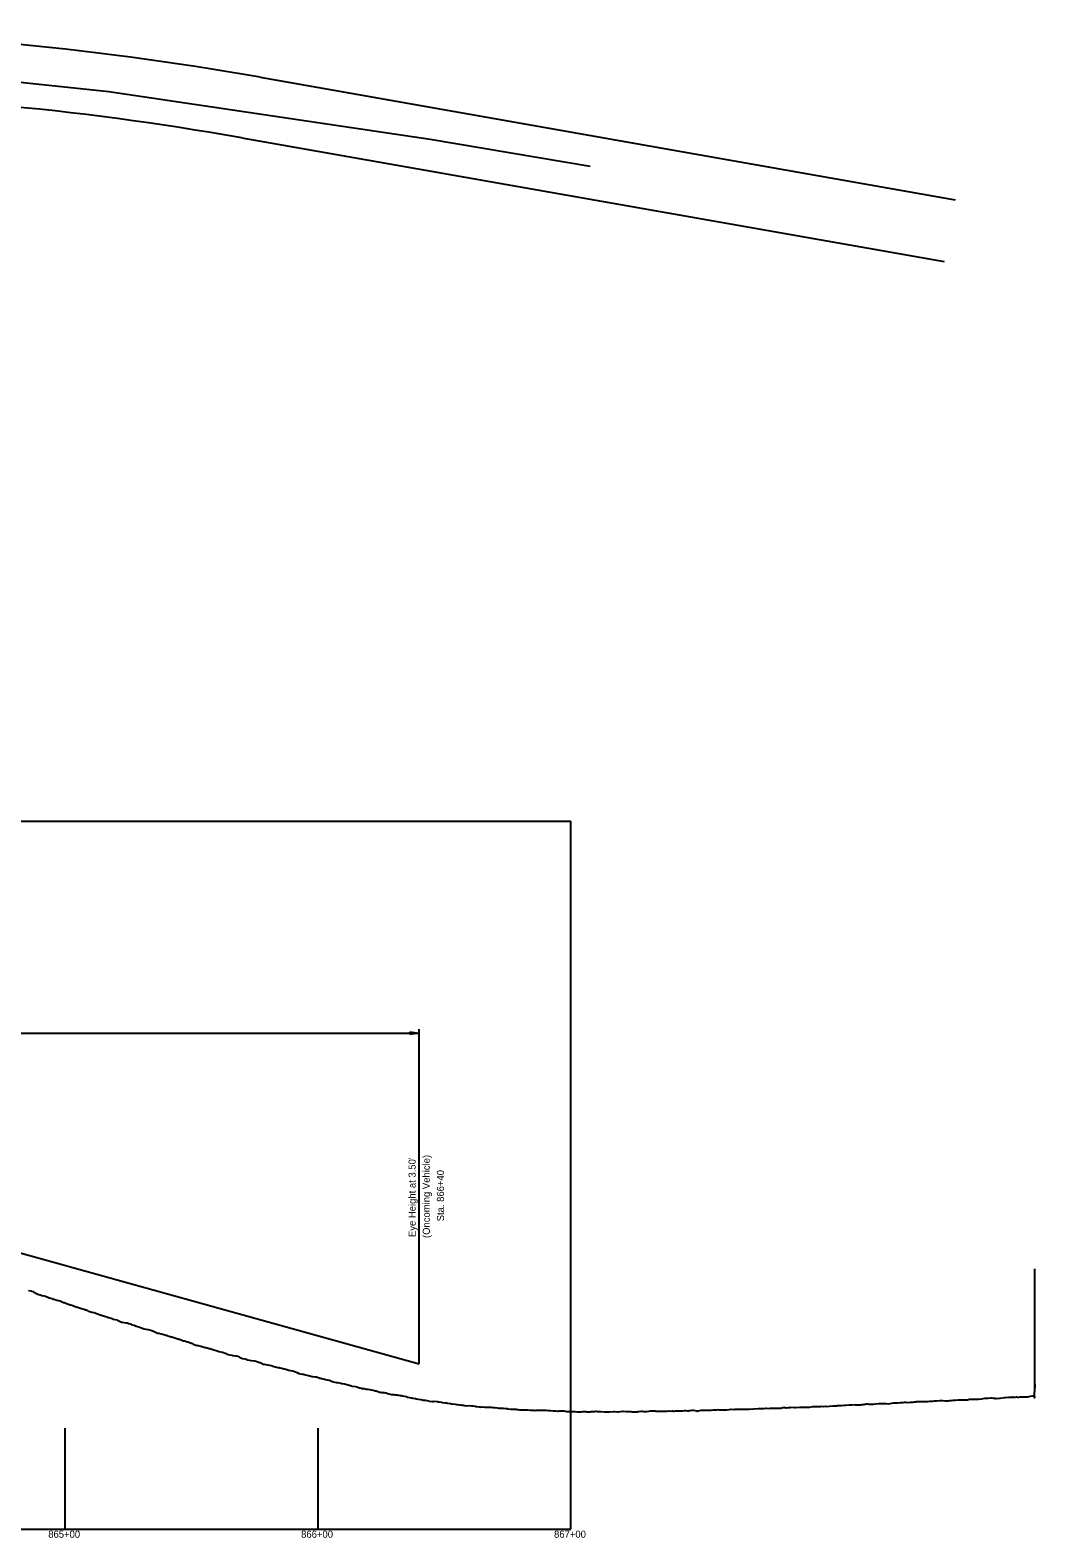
# Model space of a CAD drawing. Extents: x 115987 to 120394, y 324408 to 325987.
# Drawn here: x 119996 to 120394, y 325283 to 325879 of the extents above; entities that cross this region are included whole.
import ezdxf

# ---------------------------------------------------------------- set-up
doc = ezdxf.new("R2010")
doc.units = 0
for name, color, linetype in [('_CIVIL_CONSTRUCTION', 7, 'Continuous'), ('DR_Ditch', 7, 'Continuous'), ('DT_X_Spot_Elev', 7, 'Continuous'), ('SV_X_Text', 7, 'Continuous')]:
    doc.layers.add(name, color=color, linetype=linetype)

msp = doc.modelspace()

# ---------------------------------------------------------------- linework, layer by layer
at = {"layer": '_CIVIL_CONSTRUCTION'}
msp.add_lwpolyline([(119433.5, 325808.06), (119458.19, 325811.98), (119653.75, 325843.88), (119803.55, 325862.77), (119869.37, 325865.76), (119948.48, 325863.4), (120027.4, 325855.07), (120154.49, 325836.23), (120217.67, 325825.54)], dxfattribs=at)
at = {"layer": 'DR_Ditch'}
for p, q in [((119610.09, 325566.43), (120210.09, 325566.43)), ((120210.09, 325286.43), (120210.09, 325566.43)), ((119675.09, 325484.19), (120150.09, 325351.76)), ((119790.09, 325482.58), (120150.09, 325482.58)), ((120150.09, 325482.58), (120146.38, 325482.09)), ((120146.38, 325482.09), (120146.39, 325482.09)), ((120146.4, 325483.08), (120146.4, 325483.08)), ((120146.4, 325483.08), (120150.09, 325482.58)), ((120150.09, 325351.76), (120150.09, 325484.13)), ((120010.09, 325286.43), (120010.09, 325326.43)), ((120110.09, 325286.43), (120110.09, 325326.43)), ((119610.09, 325286.43), (120210.09, 325286.43))]:
    msp.add_line(p, q, dxfattribs=at)
msp.add_ellipse((120145.45, 325482.59), major_axis=(1.13, 0), ratio=0.8, start_param=5.69288, end_param=6.856679, dxfattribs=at)
at = {"layer": 'DT_X_Spot_Elev'}
msp.add_lwpolyline([(119995.57, 325380.85), (119996.69, 325380.64), (119996.75, 325380.63), (119996.78, 325380.62), (119997.48, 325380.41), (119997.61, 325380.34), (119998.8, 325379.67), (119999.33, 325379.35), (119999.33, 325379.35), (119999.33, 325379.35), (120000.62, 325378.94), (120000.71, 325378.9), (120000.92, 325378.89), (120001.61, 325378.76), (120002.21, 325378.64), (120002.31, 325378.61), (120002.34, 325378.6), (120002.62, 325378.47), (120002.96, 325378.31), (120003.74, 325377.96), (120003.93, 325377.87), (120004.82, 325377.61), (120005.28, 325377.46), (120005.71, 325377.34), (120006.37, 325377.15), (120006.77, 325377.04), (120007.44, 325376.89), (120007.54, 325376.87), (120008.09, 325376.68), (120008.43, 325376.55), (120008.86, 325376.35), (120009.44, 325376.1), (120009.71, 325376.02), (120010.08, 325375.91), (120010.63, 325375.66), (120011.35, 325375.38), (120011.45, 325375.36), (120011.83, 325375.21), (120012.37, 325375.11), (120013.12, 325374.83), (120013.66, 325374.69), (120013.8, 325374.65), (120014.04, 325374.55), (120014.89, 325374.26), (120015.01, 325374.22), (120015.76, 325373.98), (120016.58, 325373.73), (120016.61, 325373.72), (120016.62, 325373.71), (120017.66, 325373.43), (120018.16, 325373.2), (120018.26, 325373.16), (120018.36, 325373.12), (120019.23, 325372.68), (120019.85, 325372.49), (120019.96, 325372.45), (120020.21, 325372.39), (120020.71, 325372.27), (120021.49, 325372.12), (120021.52, 325372.11), (120021.52, 325372.11), (120022.21, 325371.88), (120022.93, 325371.58), (120023.29, 325371.46), (120023.9, 325371.21), (120023.91, 325371.21), (120024.02, 325371.18), (120024.35, 325371.08), (120024.82, 325370.93), (120025.15, 325370.83), (120025.18, 325370.82), (120025.62, 325370.67), (120026.53, 325370.38), (120027.07, 325370.21), (120027.32, 325370.15), (120028.24, 325369.83), (120028.5, 325369.73), (120028.99, 325369.55), (120029.06, 325369.53), (120030.6, 325369.2), (120030.66, 325369.19), (120030.68, 325369.18), (120030.78, 325369.13), (120032.37, 325368.34), (120032.68, 325368.25), (120034.05, 325368.04), (120034.35, 325368.02), (120034.41, 325368), (120034.56, 325367.97), (120035.69, 325367.59), (120036.3, 325367.45), (120036.39, 325367.41), (120037.2, 325367.17), (120037.4, 325367.11), (120038.21, 325366.77), (120038.23, 325366.77), (120038.3, 325366.74), (120039.17, 325366.45), (120039.23, 325366.43), (120039.85, 325366.19), (120040.91, 325365.73), (120041.02, 325365.69), (120041.03, 325365.69), (120041.13, 325365.66), (120041.33, 325365.6), (120042.82, 325365.43), (120042.87, 325365.42), (120042.89, 325365.41), (120043.95, 325365.11), (120044.43, 325364.96), (120044.57, 325364.92), (120044.59, 325364.92), (120044.7, 325364.88), (120045.07, 325364.7), (120046.06, 325364.21), (120046.26, 325364.12), (120046.29, 325364.12), (120046.58, 325364.01), (120046.62, 325364), (120046.63, 325363.99), (120047.1, 325363.91), (120048.09, 325363.74), (120048.25, 325363.68), (120049.18, 325363.38), (120049.89, 325363.18), (120050.11, 325363.11), (120050.54, 325362.96), (120051.64, 325362.58), (120051.9, 325362.55), (120052.31, 325362.45), (120053.48, 325362.05), (120053.81, 325361.92), (120055, 325361.61), (120055.15, 325361.56), (120055.31, 325361.53), (120055.58, 325361.45), (120055.95, 325361.3), (120056.77, 325360.98), (120057.05, 325360.93), (120057.26, 325360.89), (120058.03, 325360.63), (120058.48, 325360.5), (120058.57, 325360.49), (120059.01, 325360.36), (120059.96, 325360.04), (120060.16, 325359.97), (120060.37, 325359.85), (120060.74, 325359.65), (120061.78, 325359.24), (120061.94, 325359.2), (120062.05, 325359.19), (120062.44, 325359.13), (120062.81, 325359.04), (120063.73, 325358.84), (120063.91, 325358.77), (120064.11, 325358.69), (120064.55, 325358.55), (120065.46, 325358.31), (120065.73, 325358.23), (120066.21, 325358.1), (120067.07, 325357.87), (120067.26, 325357.83), (120068.46, 325357.49), (120068.6, 325357.44), (120068.74, 325357.4), (120068.91, 325357.34), (120069.85, 325357.03), (120070.19, 325356.91), (120070.58, 325356.78), (120070.8, 325356.75), (120072.36, 325356.46), (120073.78, 325355.85), (120074.07, 325355.72), (120074.29, 325355.61), (120074.46, 325355.55), (120075.97, 325355.24), (120076.1, 325355.21), (120076.4, 325355.17), (120077.39, 325355.02), (120077.66, 325354.95), (120077.78, 325354.95), (120078.35, 325354.79), (120079.23, 325354.32), (120079.35, 325354.28), (120079.6, 325354.19), (120080.23, 325353.99), (120080.35, 325353.97), (120081.2, 325353.81), (120081.72, 325353.6), (120081.98, 325353.49), (120082.12, 325353.45), (120083.03, 325353.22), (120083.48, 325353.19), (120083.54, 325353.18), (120084.81, 325353.07), (120084.86, 325353.05), (120085.05, 325353.05), (120086.24, 325352.64), (120086.64, 325352.49), (120086.71, 325352.46), (120087.41, 325352.16), (120088.45, 325351.74), (120088.82, 325351.65), (120090.06, 325351.4), (120090.26, 325351.37), (120091.38, 325351.13), (120091.6, 325351.1), (120091.9, 325351.02), (120091.93, 325351.01), (120092.6, 325350.82), (120093.08, 325350.69), (120093.22, 325350.66), (120093.6, 325350.56), (120094.23, 325350.41), (120094.73, 325350.31), (120094.96, 325350.27), (120095.14, 325350.2), (120095.81, 325350.05), (120096.54, 325349.87), (120096.8, 325349.8), (120097.37, 325349.68), (120098.45, 325349.35), (120098.58, 325349.31), (120099.25, 325349.18), (120100.46, 325348.93), (120100.5, 325348.92), (120100.55, 325348.91), (120101.81, 325348.35), (120102.45, 325348.06), (120102.57, 325348.05), (120103.15, 325347.91), (120103.88, 325347.78), (120104.2, 325347.73), (120104.36, 325347.7), (120104.4, 325347.69), (120105.12, 325347.48), (120106.23, 325347.16), (120106.86, 325347.02), (120107.81, 325346.83), (120107.97, 325346.77), (120108.92, 325346.65), (120109.4, 325346.62), (120109.72, 325346.56), (120109.83, 325346.52), (120110.48, 325346.29), (120110.86, 325346.2), (120111.2, 325346.11), (120111.48, 325346.04), (120111.96, 325345.94), (120112.54, 325345.79), (120112.91, 325345.69), (120112.94, 325345.68), (120113.04, 325345.65), (120114.31, 325345.4), (120114.48, 325345.36), (120114.51, 325345.36), (120114.67, 325345.3), (120114.9, 325345.2), (120115.35, 325345.02), (120116.18, 325344.7), (120117.32, 325344.5), (120117.71, 325344.4), (120117.82, 325344.37), (120117.9, 325344.39), (120119.14, 325344.21), (120119.55, 325344.1), (120119.7, 325344.07), (120120.58, 325343.88), (120121.5, 325343.62), (120121.58, 325343.62), (120121.97, 325343.5), (120123.29, 325343.17), (120123.61, 325343.03), (120123.73, 325342.99), (120125.04, 325342.8), (120125.14, 325342.77), (120125.43, 325342.7), (120126.46, 325342.39), (120126.63, 325342.34), (120127.25, 325342.13), (120127.28, 325342.12), (120127.37, 325342.11), (120128.31, 325342.01), (120128.77, 325341.9), (120129.12, 325341.85), (120129.53, 325341.79), (120129.93, 325341.75), (120130.71, 325341.61), (120130.87, 325341.58), (120131.06, 325341.53), (120131.7, 325341.43), (120131.96, 325341.37), (120132.74, 325341.2), (120133.13, 325341.1), (120133.49, 325340.97), (120133.74, 325340.89), (120134.4, 325340.62), (120134.98, 325340.59), (120135.28, 325340.54), (120135.44, 325340.51), (120136.29, 325340.44), (120136.96, 325340.33), (120137.09, 325340.3), (120137.29, 325340.24), (120138.06, 325340), (120138.1, 325339.99), (120138.77, 325339.76), (120138.86, 325339.75), (120139.4, 325339.69), (120139.74, 325339.66), (120140.16, 325339.63), (120140.57, 325339.61), (120141.16, 325339.54), (120141.47, 325339.5), (120141.67, 325339.47), (120142.06, 325339.43), (120142.57, 325339.33), (120143.07, 325339.23), (120143.55, 325339.17), (120143.66, 325339.16), (120144.76, 325338.89), (120144.93, 325338.84), (120145.38, 325338.67), (120146.3, 325338.51), (120146.82, 325338.4), (120147.12, 325338.39), (120147.51, 325338.3), (120148.69, 325338.08), (120148.86, 325338), (120149, 325337.98), (120149.59, 325337.88), (120150.75, 325337.72), (120150.86, 325337.7), (120151.63, 325337.5), (120152.2, 325337.45), (120152.54, 325337.39), (120152.58, 325337.41), (120153.83, 325337.15), (120153.97, 325337.13), (120154.03, 325337.11), (120155.25, 325336.98), (120155.67, 325336.96), (120155.83, 325336.99), (120157.2, 325336.89), (120157.34, 325336.88), (120157.59, 325336.81), (120158.14, 325336.73), (120158.9, 325336.71), (120159.34, 325336.59), (120160.43, 325336.39), (120160.64, 325336.38), (120161.12, 325336.33), (120161.21, 325336.32), (120161.29, 325336.31), (120162.47, 325336.17), (120162.91, 325336.06), (120163.01, 325336.03), (120163.15, 325336), (120164.37, 325335.85), (120164.88, 325335.8), (120164.97, 325335.78), (120165.38, 325335.7), (120166.22, 325335.62), (120166.44, 325335.57), (120166.89, 325335.49), (120167.57, 325335.42), (120168, 325335.38), (120168.09, 325335.37), (120168.81, 325335.27), (120169.67, 325335.31), (120169.8, 325335.31), (120169.91, 325335.31), (120170.73, 325335.25), (120171.44, 325335.23), (120171.49, 325335.23), (120172.26, 325335.05), (120172.54, 325334.98), (120172.99, 325334.92), (120173.85, 325334.82), (120174.29, 325334.78), (120174.46, 325334.74), (120175.18, 325334.77), (120176.05, 325334.65), (120176.13, 325334.64), (120177.35, 325334.72), (120177.44, 325334.72), (120177.71, 325334.7), (120178.02, 325334.67), (120178.62, 325334.62), (120179.19, 325334.57), (120179.68, 325334.52), (120179.78, 325334.51), (120179.98, 325334.49), (120180.98, 325334.36), (120181.43, 325334.34), (120181.56, 325334.33), (120182.41, 325334.32), (120183, 325334.35), (120183.41, 325334.31), (120184.31, 325334.16), (120184.82, 325334.12), (120185.19, 325334.04), (120186.29, 325333.9), (120186.6, 325333.88), (120186.71, 325333.87), (120187.02, 325333.83), (120187.76, 325333.89), (120188.22, 325333.91), (120188.48, 325333.85), (120188.77, 325333.82), (120189.16, 325333.78), (120189.8, 325333.69), (120189.98, 325333.67), (120190.57, 325333.63), (120191.15, 325333.62), (120191.43, 325333.61), (120191.64, 325333.58), (120192.35, 325333.56), (120192.94, 325333.63), (120193.94, 325333.49), (120193.97, 325333.48), (120194.02, 325333.48), (120194.03, 325333.48), (120194.52, 325333.52), (120195.47, 325333.43), (120195.79, 325333.39), (120196.03, 325333.43), (120196.12, 325333.43), (120196.17, 325333.42), (120196.4, 325333.43), (120197.67, 325333.46), (120198.01, 325333.47), (120199.34, 325333.46), (120199.55, 325333.45), (120200.3, 325333.44), (120201.09, 325333.41), (120201.43, 325333.37), (120201.97, 325333.3), (120203.09, 325333.19), (120203.36, 325333.18), (120204.08, 325333.18), (120204.89, 325333.16), (120205.06, 325333.15), (120205.42, 325333.17), (120206.84, 325333.25), (120207.34, 325333.21), (120208.38, 325333.01), (120208.67, 325332.98), (120208.73, 325332.98), (120209.34, 325332.98), (120210.25, 325332.93), (120210.71, 325332.92), (120211.19, 325332.95), (120211.54, 325332.95), (120211.71, 325332.94), (120212.6, 325332.89), (120213.01, 325332.85), (120213.18, 325332.83), (120213.94, 325332.8), (120214.33, 325332.82), (120214.78, 325332.94), (120215.75, 325332.92), (120215.93, 325332.92), (120216.06, 325332.92), (120216.41, 325332.89), (120217.17, 325332.88), (120217.75, 325332.87), (120218.12, 325332.91), (120218.92, 325332.94), (120219.43, 325332.95), (120219.75, 325333.04), (120219.93, 325333.07), (120220.47, 325333.01), (120221.13, 325332.91), (120221.31, 325332.91), (120221.83, 325332.95), (120221.86, 325332.95), (120223.27, 325332.87), (120223.31, 325332.86), (120223.67, 325332.89), (120224.74, 325332.82), (120225.13, 325332.84), (120225.35, 325332.86), (120226.89, 325332.97), (120227.03, 325332.98), (120227.07, 325332.98), (120227.46, 325332.96), (120228.38, 325332.9), (120228.75, 325332.87), (120228.77, 325332.88), (120228.79, 325332.88), (120230.57, 325333.07), (120230.58, 325333.08), (120230.59, 325333.07), (120230.63, 325333.07), (120231.98, 325332.94), (120232.24, 325332.91), (120232.3, 325332.92), (120232.86, 325332.93), (120233.52, 325332.99), (120234, 325332.92), (120234.17, 325332.9), (120234.97, 325332.88), (120235.77, 325332.82), (120236.01, 325332.81), (120236.28, 325332.87), (120236.49, 325332.95), (120236.99, 325332.99), (120237.86, 325333.09), (120237.99, 325333.09), (120238.23, 325333.08), (120238.82, 325333.03), (120239.73, 325332.92), (120239.83, 325332.96), (120240.09, 325332.95), (120240.83, 325333.1), (120241.55, 325333.28), (120241.85, 325333.27), (120243.06, 325333.22), (120243.36, 325333.21), (120243.48, 325333.17), (120243.57, 325333.15), (120243.76, 325333.16), (120245.2, 325333.09), (120245.42, 325333.08), (120246.09, 325333.05), (120246.97, 325333.04), (120247.08, 325333.07), (120247.31, 325333.04), (120247.98, 325333.09), (120248.77, 325333.17), (120248.93, 325333.17), (120249.92, 325333.16), (120250.2, 325333.17), (120250.62, 325333.13), (120250.86, 325333.11), (120251.47, 325333.18), (120251.7, 325333.19), (120252.51, 325333.23), (120252.54, 325333.24), (120252.64, 325333.24), (120253.35, 325333.25), (120253.43, 325333.24), (120254.31, 325333.24), (120254.97, 325333.31), (120255.51, 325333.3), (120256.13, 325333.29), (120256.54, 325333.29), (120256.87, 325333.32), (120257.37, 325333.38), (120258.07, 325333.45), (120258.3, 325333.46), (120258.6, 325333.48), (120259.69, 325333.21), (120259.93, 325333.16), (120259.94, 325333.16), (120260.44, 325333.27), (120261.52, 325333.46), (120261.98, 325333.53), (120262.28, 325333.53), (120263.21, 325333.51), (120263.9, 325333.45), (120263.96, 325333.44), (120265.25, 325333.49), (120265.39, 325333.5), (120265.6, 325333.49), (120266.38, 325333.58), (120266.88, 325333.63), (120267.36, 325333.66), (120267.56, 325333.66), (120267.78, 325333.66), (120268.39, 325333.72), (120268.63, 325333.68), (120269.14, 325333.62), (120269.98, 325333.58), (120270.08, 325333.58), (120270.58, 325333.58), (120270.84, 325333.58), (120271.09, 325333.6), (120271.72, 325333.69), (120272.56, 325333.73), (120272.71, 325333.74), (120272.79, 325333.75), (120273.33, 325333.86), (120273.48, 325333.86), (120274.66, 325333.82), (120274.95, 325333.86), (120276.03, 325333.83), (120276.71, 325333.85), (120276.82, 325333.85), (120277.34, 325333.89), (120278.54, 325333.85), (120278.72, 325333.85), (120278.92, 325333.86), (120280.42, 325333.93), (120280.59, 325333.93), (120282.3, 325333.99), (120282.38, 325333.99), (120282.38, 325333.99), (120282.39, 325333.99), (120284.07, 325334.15), (120284.09, 325334.15), (120284.14, 325334.15), (120285.61, 325334.11), (120285.71, 325334.11), (120286.07, 325334.12), (120286.3, 325334.1), (120287.27, 325334.26), (120287.53, 325334.25), (120288.3, 325334.19), (120288.86, 325334.22), (120289.23, 325334.22), (120289.7, 325334.24), (120290.53, 325334.26), (120290.64, 325334.22), (120291.23, 325334.25), (120291.68, 325334.29), (120292.1, 325334.35), (120292.53, 325334.33), (120293.09, 325334.33), (120293.72, 325334.55), (120294.19, 325334.57), (120294.97, 325334.54), (120295.37, 325334.47), (120295.46, 325334.47), (120296.12, 325334.53), (120296.7, 325334.56), (120297.04, 325334.62), (120297.1, 325334.62), (120298.49, 325334.52), (120298.64, 325334.51), (120298.68, 325334.52), (120298.97, 325334.53), (120300.41, 325334.67), (120300.5, 325334.68), (120300.64, 325334.68), (120302.21, 325334.69), (120302.45, 325334.69), (120302.99, 325334.68), (120304.15, 325334.69), (120304.33, 325334.7), (120304.52, 325334.74), (120305.75, 325334.91), (120305.94, 325334.92), (120307.33, 325334.96), (120307.44, 325334.98), (120307.55, 325335), (120307.64, 325335), (120308.11, 325335), (120308.82, 325335.01), (120309.03, 325335.03), (120310.02, 325334.95), (120310.04, 325334.95), (120310.05, 325334.95), (120310.74, 325335.04), (120311.28, 325335.01), (120312.15, 325335.09), (120312.3, 325335.1), (120312.37, 325335.1), (120313.71, 325335.19), (120313.74, 325335.19), (120313.8, 325335.19), (120315.28, 325335.27), (120315.4, 325335.3), (120315.62, 325335.31), (120316.9, 325335.36), (120317.06, 325335.37), (120317.96, 325335.42), (120318.56, 325335.46), (120318.66, 325335.45), (120318.83, 325335.49), (120320.17, 325335.57), (120320.51, 325335.58), (120320.59, 325335.59), (120321.29, 325335.61), (120322.42, 325335.67), (120322.49, 325335.65), (120323.4, 325335.63), (120323.98, 325335.62), (120324.27, 325335.63), (120324.35, 325335.64), (120324.7, 325335.66), (120325.17, 325335.72), (120325.81, 325335.8), (120325.92, 325335.81), (120326.53, 325335.89), (120327.01, 325335.94), (120327.41, 325335.97), (120327.93, 325335.87), (120328.75, 325335.87), (120329.09, 325335.88), (120329.32, 325335.9), (120329.71, 325335.89), (120330.57, 325336.01), (120331.69, 325336.1), (120331.74, 325336.1), (120331.98, 325336.11), (120332.94, 325336.11), (120333.39, 325336.11), (120333.56, 325336.11), (120333.87, 325336.11), (120334.67, 325336.1), (120334.77, 325336.09), (120335.5, 325336.01), (120336.32, 325336.11), (120336.33, 325336.11), (120336.35, 325336.12), (120337.61, 325336.34), (120337.8, 325336.38), (120338.15, 325336.39), (120339.16, 325336.43), (120339.52, 325336.42), (120340.32, 325336.51), (120340.78, 325336.54), (120340.97, 325336.54), (120341.52, 325336.56), (120341.99, 325336.61), (120342.5, 325336.66), (120343.05, 325336.55), (120343.24, 325336.53), (120344.22, 325336.63), (120344.68, 325336.64), (120344.96, 325336.63), (120345.25, 325336.69), (120345.94, 325336.8), (120346.46, 325336.83), (120346.6, 325336.84), (120346.69, 325336.86), (120347.7, 325336.93), (120348.33, 325336.86), (120349.11, 325336.9), (120349.29, 325336.91), (120350.01, 325336.87), (120350.11, 325336.88), (120350.18, 325336.89), (120351.08, 325336.96), (120351.87, 325337.03), (120351.99, 325337.04), (120352.33, 325337.07), (120352.91, 325337.11), (120353.25, 325337.09), (120353.88, 325337.12), (120354.53, 325337.2), (120354.7, 325337.22), (120354.76, 325337.22), (120355.86, 325337.29), (120356.18, 325337.32), (120356.45, 325337.32), (120357.2, 325337.27), (120357.88, 325337.19), (120358.21, 325337.22), (120359.31, 325337.22), (120359.74, 325337.29), (120360.54, 325337.38), (120361.18, 325337.46), (120361.41, 325337.47), (120361.53, 325337.49), (120361.59, 325337.5), (120362.01, 325337.51), (120363.11, 325337.55), (120363.31, 325337.54), (120364.35, 325337.6), (120364.53, 325337.61), (120364.92, 325337.62), (120365.09, 325337.59), (120365.48, 325337.62), (120366.1, 325337.59), (120366.95, 325337.55), (120366.95, 325337.55), (120366.96, 325337.56), (120367.74, 325337.86), (120368.21, 325337.84), (120368.93, 325337.81), (120369.35, 325337.84), (120369.44, 325337.83), (120369.48, 325337.83), (120370.83, 325337.79), (120370.84, 325337.79), (120370.85, 325337.79), (120371.31, 325337.83), (120372.37, 325337.97), (120372.62, 325338.01), (120373.08, 325338.14), (120373.69, 325338.19), (120374.23, 325338.19), (120374.64, 325338.25), (120374.82, 325338.26), (120375.09, 325338.26), (120376, 325338.31), (120376.48, 325338.33), (120377.05, 325338.26), (120377.77, 325338.2), (120378.11, 325338.17), (120378.33, 325338.17), (120379.5, 325338.18), (120379.61, 325338.18), (120379.86, 325338.23), (120381.53, 325338.54), (120381.6, 325338.55), (120381.61, 325338.55), (120381.65, 325338.55), (120381.67, 325338.56), (120381.81, 325338.56), (120383.13, 325338.68), (120383.42, 325338.63), (120384.48, 325338.7), (120384.64, 325338.71), (120384.98, 325338.7), (120385.26, 325338.67), (120385.71, 325338.67), (120386.29, 325338.73), (120386.7, 325338.68), (120387.08, 325338.68), (120387.74, 325338.73), (120387.8, 325338.74), (120388.25, 325338.76), (120388.91, 325338.79), (120389.07, 325338.81), (120389.48, 325338.82), (120390.41, 325338.82), (120390.76, 325338.82), (120391.18, 325338.96), (120391.86, 325339.05), (120392.54, 325339.12), (120392.66, 325339.14), (120392.84, 325339.17), (120393.04, 325339.12), (120393.17, 325339.02), (120393.19, 325339.03), (120393.26, 325338.9), (120393.34, 325338.84), (120393.35, 325338.81), (120393.45, 325338.31), (120393.48, 325343.27), (120393.48, 325343.69), (120393.5, 325342.3), (120393.5, 325344.38), (120393.51, 325357.22), (120393.51, 325365.14), (120393.52, 325389.41)], dxfattribs=at)
at = {"layer": 'SV_X_Text'}
for p, q in [((120087.23, 325860.7), (120361.96, 325812.24)), ((120079.9, 325836.73), (120357.64, 325787.75))]:
    msp.add_line(p, q, dxfattribs=at)
for centre, radius, end in [((119874.46, 324654.32), 1225, 99.38348), ((119875.82, 324679.59), 1175, 99.35674)]:
    msp.add_arc(centre, radius, 79.99759, end, dxfattribs=at)

# ---------------------------------------------------------------- texts
at = {"layer": 'DR_Ditch'}
for s, p in [("Eye Height at 3.50'", (120148.69, 325401.96)), ('(Oncoming Vehicle)', (120154.29, 325401.58)), ('Sta. 866+40', (120159.89, 325408.18))]:
    msp.add_text(s, height=2.8, rotation=90, dxfattribs=at).set_placement(p)
for s, p in [('865+00', (120003.41, 325283.03)), ('866+00', (120103.41, 325283.03)), ('867+00', (120203.41, 325283.03))]:
    msp.add_text(s, height=2.8, dxfattribs=at).set_placement(p)

doc.saveas('drawing.dxf')
